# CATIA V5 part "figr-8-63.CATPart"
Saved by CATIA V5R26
Part number: Part1
Bounding box of the stored display mesh (mm): x -68.924 to 54.237, y -54.052 to 120.856, z 0 to 40
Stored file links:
  D:\_Deepak\CATIA\CATIA V5-6R2016_Deepak\Resources\Part files\Partfiles\c08_catia_v5_6r2016_prt\figr-8-63.CATPart
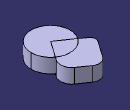
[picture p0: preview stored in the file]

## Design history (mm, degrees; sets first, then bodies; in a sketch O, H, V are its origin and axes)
Body1 (main body)
  Sketch1 on xy-plane, origin (0, 0, 0), H (1, 0, 0), V (0, 1, 0)
    circle A1 centre (0, 0) radius 54.2371
    point P1 (0, 54.2371)
    coincidence: A1 P1, P1 V
  Pad1: profile Sketch1, direction (0, 0, 1), length 40
Body2
  Sketch2 on xy-plane, origin (0, 0, 0), H (1, 0, 0), V (0, 1, 0)
    line L1 (0, 0) -> (36.9865, 52.8223)
    arc A1 centre (11.6298, 70.5772) radius 30.9549 from (36.9865, 52.8223) to (29.3848, 95.934) ccw
    line L2 (29.3848, 95.934) -> (0.2008, 116.3688)
    arc A2 centre (-14.1853, 95.8234) radius 25.0814 from (0.2008, 116.3688) to (-34.7307, 110.2094) ccw
    line L3 (-34.7307, 110.2094) -> (-66.0893, 65.4248)
    arc A3 centre (-53.2403, 56.4279) radius 15.6856 from (-66.0893, 65.4248) to (-62.2373, 43.579) ccw
    line L4 (-62.2373, 43.579) -> (0, 0)
    tangency: A1 L1, L2 A1, A2 L2, L3 A2, A3 L3, L4 A3
  Pad2: profile Sketch2, direction (0, 0, 1), length 40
